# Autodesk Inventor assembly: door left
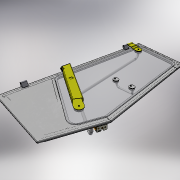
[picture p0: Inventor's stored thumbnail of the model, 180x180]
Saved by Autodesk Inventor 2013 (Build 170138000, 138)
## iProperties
Shininess: 64.0
Length Units: 11269
Angle Units: 11279
Time Units: 11290
Mass Units: 11283
Length Display Precision: 3
Angle Display Precision: 2
Compacted: True
Created: 2005-02
Part Number: door left
Document SubType Name: Assembly
Designer: =<Author>
Manufacturer: Standard
Standards Organization: Custom
Description: Left door
Density: 0.0
Volumn: 0.0
Area: 0.0
PropertySet Name: Model Information
Control State: 0
Master: False
Checked Out: False
Checked Out Date: 2008-10-15
Last Check In Date: 2008-10-15
Author: PVitaliy
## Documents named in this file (24)
- C:\Users\tedescj\Desktop\Assy, Door\_Data\Assy, Cab\door left.iam
- C:\Users\tedescj\Desktop\Assy, Door\_Data\Assy, Cab\PK46.51.11.011.ipt
- C:\Users\tedescj\Desktop\Assy, Door\_Data\Assy, Cab\PK46.51.11.014.ipt
- C:\Users\tedescj\Desktop\Assy, Door\_Data\Assy, Cab\PK46.51.11.013.ipt
- C:\Users\tedescj\Desktop\Assy, Door\_Data\Assy, Cab\PK46.51.11.021.ipt
- C:\Users\tedescj\Desktop\Assy, Door\_Data\Assy, Cab\PK46.51.11.023.ipt
- C:\Users\tedescj\Desktop\Assy, Door\_Data\Assy, Cab\PK46.51.11.025.ipt
- C:\Users\tedescj\Desktop\Assy, Door\_Data\Assy, Cab\PK46.51.11.024.ipt
- C:\Users\tedescj\Desktop\Assy, Door\_Data\Assy, Cab\PK46.51.11.031.ipt
- C:\Users\tedescj\Desktop\Assy, Door\_Data\Assy, Cab\PK46.51.11.033.ipt
- C:\Users\tedescj\Desktop\Assy, Door\_Data\Assy, Cab\PK46.51.11.035.ipt
- C:\Users\tedescj\Desktop\Assy, Door\_Data\Assy, Cab\PK46.51.11.034.ipt
- C:\Users\tedescj\Desktop\Assy, Door\_Data\Assy, Cab\PK46.51.11.022.ipt
- C:\Users\tedescj\Desktop\Assy, Door\_Data\Assy, Cab\PK46.51.11.032.ipt
- C:\Users\tedescj\Desktop\Assy, Door\_Data\Assy, Cab\PK46.51.11.012(new).ipt
- C:\Users\tedescj\Desktop\Assy, Door\_Data\Assy, Cab\PK46.51.11.015.ipt
- C:\Users\tedescj\Desktop\Assy, Door\_Data\Assy, Cab\PK46.51.11.026.ipt
- C:\Users\tedescj\Desktop\Assy, Door\_Data\Assy, Cab\Support gas.ipt
- C:\Users\tedescj\Desktop\Assy, Door\_Data\Assy, Cab\PK46.51.11.040.iam
- C:\Users\tedescj\Desktop\Assy, Door\_Data\Assy, Cab\PK46.51.11.016-01.ipt
- C:\Users\tedescj\Desktop\Assy, Door\_Data\Assy, Cab\PK46.51.11.016.ipt
- C:\Users\tedescj\Desktop\Assy, Door\_Data\Assy, Cab\2108-6105015.iam
- C:\Users\tedescj\Desktop\Assy, Door\_Data\Assy, Cab\integral hinge.ipt
- C:\Users\tedescj\Desktop\Assy, Door\_Data\Assy, Cab\Glass door assembly new.iam
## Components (24 placed, 23 different names)
1. PK46.51.11.011:1 — Flush:1, Flush:2, Mate:1, Mate:5, Mate:9, Mate:18, Mate:19, Mate:34, Flush:20, Mate:39, Mate:42, Mate:43, Flush:24
2. PK46.51.11.013:1 — Mate:2, Flush:3, Flush:4, Mate:7, Mate:10, Flush:18, Mate:45, Flush:25, Mate:47, Flush:26
3. PK46.51.11.014:1 — Flush:1, Flush:2, Mate:1, Mate:2, Flush:3, Flush:4, Mate:4, Mate:8, Flush:9, Mate:44
4. PK46.51.11.015:1 — Mate:45, Tangent:1, Tangent:2, Angle:1
5. PK46.51.11.016:1 — Flush:23, Mate:37, Mate:38
6. PK46.51.11.016-01:1 — Mate:36, Flush:21, Flush:22, Flush:23, Mate:38
7. PK46.51.11.021:1 — Mate:4, Mate:6, Mate:8, Flush:7, Flush:8, Mate:14, Mate:35, Mate:37, Tangent:2
8. PK46.51.11.022:1 — Mate:18, Mate:19, Mate:20, Mate:21, Mate:40, Mate:41
9. PK46.51.11.023:1 — Mate:5, Mate:6, Mate:9, Flush:7, Mate:15, Mate:20, Mate:36, Flush:21, Flush:22
10. PK46.51.11.024:1 — Mate:17, Mate:46, Flush:27, Mate:48
11. PK46.51.11.025:1 — Mate:7, Mate:10, Flush:8, Flush:10, Mate:16, Mate:28, Flush:19, Tangent:1, Mate:48
12. PK46.51.11.026:1 — Mate:34, Flush:20, Mate:35, Angle:1
13. PK46.51.11.031:1 — Mate:14, Flush:9, Flush:10, Flush:11, Flush:13, Mate:33
14. PK46.51.11.032:1 — Mate:21, Flush:16
15. PK46.51.11.033:1 — Mate:15, Flush:11, Flush:16, Mate:33
16. PK46.51.11.034:1 — Mate:17, Flush:14
17. PK46.51.11.035:1 — Mate:16, Flush:13, Flush:14
18. PK46.51.11.040:1 [sub-assembly] — Mate:39, Mate:40, Mate:41, Insert:1, Insert:2
19. Support gas:1 — Mate:28, Flush:18, Flush:19
20. 2108-6105015:1 [sub-assembly] — Insert:1, Insert:2
21. integral hinge:1 — Insert:3, Mate:44, Insert:4
22. integral hinge:2 — Mate:42, Mate:43, Flush:24, Insert:3
23. PK46.51.11.012(new):1 — Mate:46, Flush:25, Mate:47, Flush:26, Flush:27
24. Glass door assembly new:1 [sub-assembly] — Insert:4
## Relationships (63: Mate 34, Flush 22, Insert 4, Tangent 2, Angle 1)
- Flush:1: PK46.51.11.011:1 ↔ PK46.51.11.014:1
- Flush:2: PK46.51.11.011:1 ↔ PK46.51.11.014:1
- Mate:1: PK46.51.11.011:1 ↔ PK46.51.11.014:1
- Mate:2: PK46.51.11.013:1 ↔ PK46.51.11.014:1
- Flush:3: PK46.51.11.013:1 ↔ PK46.51.11.014:1
- Flush:4: PK46.51.11.013:1 ↔ PK46.51.11.014:1
- Mate:4: PK46.51.11.014:1 ↔ PK46.51.11.021:1
- Mate:5: PK46.51.11.011:1 ↔ PK46.51.11.023:1
- Mate:6: PK46.51.11.021:1 ↔ PK46.51.11.023:1
- Mate:7: PK46.51.11.013:1 ↔ PK46.51.11.025:1
- Mate:8: PK46.51.11.014:1 ↔ PK46.51.11.021:1
- Mate:9: PK46.51.11.011:1 ↔ PK46.51.11.023:1
- Flush:7: PK46.51.11.021:1 ↔ PK46.51.11.023:1
- Mate:10: PK46.51.11.013:1 ↔ PK46.51.11.025:1
- Flush:8: PK46.51.11.021:1 ↔ PK46.51.11.025:1
- Mate:14: PK46.51.11.021:1 ↔ PK46.51.11.031:1
- Flush:9: PK46.51.11.014:1 ↔ PK46.51.11.031:1
- Flush:10: PK46.51.11.025:1 ↔ PK46.51.11.031:1
- Mate:15: PK46.51.11.023:1 ↔ PK46.51.11.033:1
- Flush:11: PK46.51.11.031:1 ↔ PK46.51.11.033:1
- Mate:16: PK46.51.11.025:1 ↔ PK46.51.11.035:1
- Flush:13: PK46.51.11.031:1 ↔ PK46.51.11.035:1
- Mate:17: PK46.51.11.024:1 ↔ PK46.51.11.034:1
- Flush:14: PK46.51.11.034:1 ↔ PK46.51.11.035:1
- Mate:18: PK46.51.11.011:1 ↔ PK46.51.11.022:1
- Mate:19: PK46.51.11.011:1 ↔ PK46.51.11.022:1
- Mate:20: PK46.51.11.022:1 ↔ PK46.51.11.023:1
- Mate:21: PK46.51.11.022:1 ↔ PK46.51.11.032:1
- Flush:16: PK46.51.11.032:1 ↔ PK46.51.11.033:1
- Mate:28: PK46.51.11.025:1 ↔ Support gas:1
- Flush:18: PK46.51.11.013:1 ↔ Support gas:1
- Flush:19: PK46.51.11.025:1 ↔ Support gas:1
- Mate:33: PK46.51.11.031:1 ↔ PK46.51.11.033:1
- Mate:34: PK46.51.11.011:1 ↔ PK46.51.11.026:1
- Flush:20: PK46.51.11.011:1 ↔ PK46.51.11.026:1
- Mate:35: PK46.51.11.021:1 ↔ PK46.51.11.026:1
- Mate:36: PK46.51.11.016-01:1 ↔ PK46.51.11.023:1
- Flush:21: PK46.51.11.016-01:1 ↔ PK46.51.11.023:1
- Flush:22: PK46.51.11.016-01:1 ↔ PK46.51.11.023:1
- Flush:23: PK46.51.11.016:1 ↔ PK46.51.11.016-01:1
- Mate:37: PK46.51.11.016:1 ↔ PK46.51.11.021:1
- Mate:38: PK46.51.11.016:1 ↔ PK46.51.11.016-01:1
- Mate:39: PK46.51.11.011:1 ↔ PK46.51.11.040:1
- Mate:40: PK46.51.11.022:1 ↔ PK46.51.11.040:1
- Mate:41: PK46.51.11.022:1 ↔ PK46.51.11.040:1
- Insert:1: PK46.51.11.040:1 ↔ 2108-6105015:1
- Insert:2: PK46.51.11.040:1 ↔ 2108-6105015:1
- Mate:42: PK46.51.11.011:1 ↔ integral hinge:2
- Mate:43: PK46.51.11.011:1 ↔ integral hinge:2
- Flush:24: PK46.51.11.011:1 ↔ integral hinge:2
- Insert:3: integral hinge:1 ↔ integral hinge:2
- Mate:44: PK46.51.11.014:1 ↔ integral hinge:1
- Mate:45: PK46.51.11.013:1 ↔ PK46.51.11.015:1
- Tangent:1: PK46.51.11.015:1 ↔ PK46.51.11.025:1
- Tangent:2: PK46.51.11.015:1 ↔ PK46.51.11.021:1
- Angle:1: PK46.51.11.015:1 ↔ PK46.51.11.026:1
- Mate:46: PK46.51.11.024:1 ↔ PK46.51.11.012(new):1
- Flush:25: PK46.51.11.013:1 ↔ PK46.51.11.012(new):1
- Mate:47: PK46.51.11.013:1 ↔ PK46.51.11.012(new):1
- Flush:26: PK46.51.11.013:1 ↔ PK46.51.11.012(new):1
- Flush:27: PK46.51.11.024:1 ↔ PK46.51.11.012(new):1
- Mate:48: PK46.51.11.024:1 ↔ PK46.51.11.025:1
- Insert:4: integral hinge:1 ↔ Glass door assembly new:1
